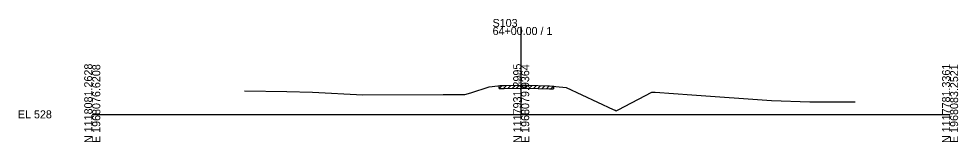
# Model space of a CAD drawing. Extents: x 974 to 1303, y 990 to 14518.
# Drawn here: x 974.3 to 1302.8, y 8490.3 to 8533.3 of the extents above; entities that cross this region are included whole.
import ezdxf

# ---------------------------------------------------------------- set-up
doc = ezdxf.new("R2010")
doc.units = 0
for name, color, linetype in [('Level 10', 7, 'Continuous'), ('Level 60', 7, 'Continuous'), ('Level 61', 7, 'Continuous'), ('Level 63', 7, 'Continuous')]:
    doc.layers.add(name, color=color, linetype=linetype)

msp = doc.modelspace()

# ---------------------------------------------------------------- linework, layer by layer
at = {"layer": 'Level 60'}
for p, q in [((1132.37, 8507.47), (1138.81, 8509.65)), ((1138.81, 8509.65), (1141.88, 8509.95)), ((1141.88, 8509.95), (1142.48, 8510.02)), ((1142.48, 8510.02), (1144.04, 8510.02)), ((1144.04, 8510.02), (1150, 8510.13)), ((1150, 8510.13), (1151.89, 8510.16)), ((1151.89, 8510.16), (1159.91, 8509.91)), ((1159.91, 8509.91), (1161.44, 8509.84)), ((1161.44, 8509.84), (1162.15, 8509.77)), ((1162.15, 8509.77), (1165.74, 8509.32)), ((1165.74, 8509.32), (1182.19, 8501.73)), ((1053.23, 8508.25), (1068.02, 8508)), ((1068.02, 8508), (1077.01, 8507.72)), ((1077.01, 8507.72), (1094.6, 8506.78)), ((1094.6, 8506.78), (1122.68, 8506.92)), ((1122.68, 8506.92), (1130.25, 8506.88)), ((1130.25, 8506.88), (1132.37, 8507.47)), ((1183.95, 8501.59), (1195.7, 8507.77)), ((1195.7, 8507.77), (1196.86, 8507.74)), ((1196.86, 8507.74), (1209.64, 8506.87)), ((1209.64, 8506.87), (1237.6, 8504.79)), ((1237.6, 8504.79), (1250.94, 8504.37)), ((1250.94, 8504.37), (1266.77, 8504.43)), ((1182.19, 8501.73), (1182.87, 8501.46)), ((1182.87, 8501.46), (1183.22, 8501.24)), ((1183.22, 8501.24), (1183.95, 8501.59))]:
    msp.add_line(p, q, dxfattribs=at)
at = {"layer": 'Level 61'}
for p, q in [((1142.34, 8509), (1143.36, 8510.02)), ((1142.34, 8509), (1142.34, 8510)), ((1142.34, 8509), (1142.48, 8509.02)), ((1142.48, 8509.02), (1144.04, 8509.02)), ((1143.84, 8509.02), (1144.85, 8510.04)), ((1144.04, 8509.02), (1150, 8509.13)), ((1145.34, 8509.05), (1146.35, 8510.06)), ((1146.84, 8509.07), (1147.85, 8510.09)), ((1148.34, 8509.1), (1149.35, 8510.12)), ((1149.84, 8509.12), (1150.85, 8510.14)), ((1150, 8509.13), (1151.89, 8509.16)), ((1151.34, 8509.15), (1152.33, 8510.15)), ((1151.89, 8509.16), (1159.91, 8508.91)), ((1152.84, 8509.13), (1153.81, 8510.1)), ((1154.34, 8509.08), (1155.31, 8510.05)), ((1155.84, 8509.03), (1156.81, 8510)), ((1157.34, 8508.99), (1158.31, 8509.96)), ((1158.84, 8508.94), (1159.81, 8509.91)), ((1160.34, 8508.89), (1161.3, 8509.85)), ((1161.31, 8509.85), (1161.31, 8508.85)), ((1159.91, 8508.91), (1161.31, 8508.85))]:
    msp.add_line(p, q, dxfattribs=at)
at = {"layer": 'Level 63'}
for p, q in [((1150, 8500), (1150, 8530.48)), ((1000, 8500), (1150, 8500)), ((1150, 8500), (1300, 8500))]:
    msp.add_line(p, q, dxfattribs=at)

# ---------------------------------------------------------------- texts
at = {"layer": 'Level 10'}
msp.add_text('538.13', height=0.9, rotation=90, dxfattribs=at).set_placement((1149.95, 8510.63))
at = {"layer": 'Level 63'}
for s, p in [('S103', (1140, 8530.48)), ('64+00.00 / 1', (1140, 8527.68)), ('EL 528', (974, 8498.6))]:
    msp.add_text(s, height=2.8, dxfattribs=at).set_placement(p)
for s, p in [('N 1118081.2628', (1000, 8490)), ('E 1968076.6208', (1002.8, 8490)), ('N 1117931.2995', (1150, 8490)), ('E 1968079.9364', (1152.8, 8490)), ('N 1117781.3361', (1300, 8490)), ('E 1968083.2521', (1302.8, 8490))]:
    msp.add_text(s, height=2.8, rotation=90, dxfattribs=at).set_placement(p)

doc.saveas('drawing.dxf')
